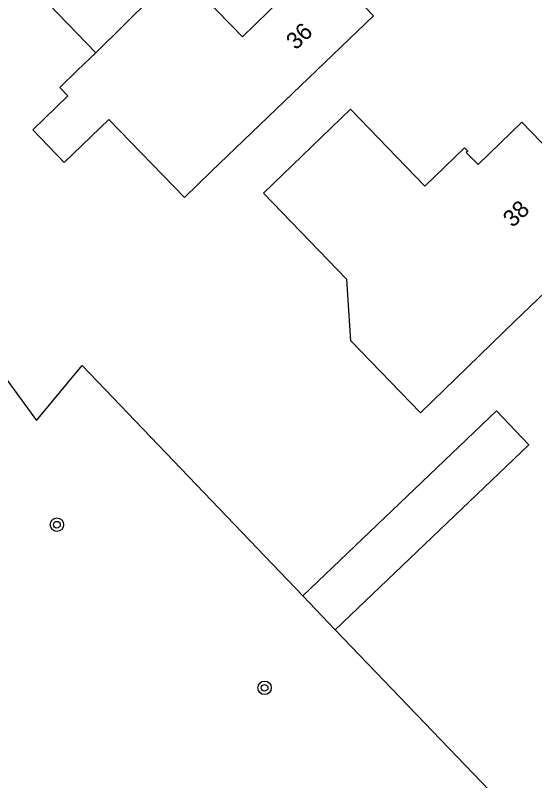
# Model space of a CAD drawing. Extents: x 137999 to 141000, y 397500 to 400501.
# Drawn here: x 138485.55 to 138516.5, y 399190.37 to 399235.95 of the extents above; entities that cross this region are included whole.
import ezdxf

# ---------------------------------------------------------------- set-up
doc = ezdxf.new("R2010")
doc.units = 0
for name, color, linetype in [('gg-afsc-erfafscheiding', 7, 'Continuous'), ('gg-anno-huisnummerreeks BGT', 7, 'Continuous'), ('gg-bbg-gedigitaliseerde bebouwing', 7, 'Continuous'), ('gg-bbg-gedigitaliseerde bijgebouw', 7, 'Continuous'), ('gg-bbg-hoofdgebouw', 7, 'Continuous'), ('gg-bbg-tussenscheiding', 7, 'Continuous'), ('gt-symb-boom', 7, 'Continuous')]:
    doc.layers.add(name, color=color, linetype=linetype)

# ---------------------------------------------------------------- blocks, each defined once
blk = doc.blocks.new('gt0-BOOM')
at = {"layer": 'gt-symb-boom'}
for radius in [0.4, 0.2]:
    blk.add_circle((0, 0), radius, dxfattribs=at)

msp = doc.modelspace()

# ---------------------------------------------------------------- linework, layer by layer
at = {"layer": 'gg-afsc-erfafscheiding'}
msp.add_line((138504.613, 399199.363), (138515.107, 399188.439), dxfattribs=at)
msp.add_lwpolyline([(138478.709, 399222.597), (138479.713, 399221.541), (138486.818, 399211.819), (138489.532, 399215.096), (138502.676, 399201.384)], dxfattribs=at)
at = {"layer": 'gg-bbg-gedigitaliseerde bebouwing'}
for p, q in [((138497.229, 399226.651), (138506.9, 399235.92)), ((138490.35, 399233.722), (138489.266, 399232.674)), ((138515.32, 399217.73), (138518.92, 399221.21))]:
    msp.add_line(p, q, dxfattribs=at)
for points in [[(138483.408, 399240.912), (138482.282, 399239.823), (138484.714, 399237.307), (138485.836, 399238.391), (138490.35, 399233.722)], [(138489.266, 399232.674), (138488.203, 399231.659), (138488.684, 399231.155), (138486.589, 399229.126), (138488.472, 399227.182), (138491.123, 399229.75), (138495.627, 399225.1), (138497.229, 399226.651)], [(138505.52, 399230.36), (138500.343, 399225.356), (138505.313, 399220.214)], [(138515.32, 399217.73), (138509.696, 399212.284), (138505.544, 399216.571), (138505.313, 399220.214)]]:
    msp.add_lwpolyline(points, dxfattribs=at)
at = {"layer": 'gg-bbg-gedigitaliseerde bijgebouw'}
msp.add_line((138502.676, 399201.384), (138504.613, 399199.363), dxfattribs=at)
msp.add_lwpolyline([(138504.613, 399199.363), (138516.149, 399210.376), (138514.215, 399212.401), (138502.676, 399201.384)], dxfattribs=at)
at = {"layer": 'gg-bbg-hoofdgebouw'}
for points in [[(138506.9, 399235.92), (138503.74, 399239.21), (138499.09, 399234.67), (138495.28, 399238.59)], [(138505.52, 399230.36), (138509.95, 399225.77), (138512.32, 399228.05), (138512.51, 399227.86), (138512.42, 399227.78), (138513.12, 399227.06), (138515.73, 399229.59), (138520.81, 399224.33), (138518.13, 399221.74), (138518.59, 399221.26), (138518.73, 399221.4), (138518.92, 399221.21)]]:
    msp.add_lwpolyline(points, dxfattribs=at)
at = {"layer": 'gg-bbg-tussenscheiding'}
msp.add_line((138495.28, 399238.59), (138490.35, 399233.722), dxfattribs=at)

# ---------------------------------------------------------------- block references
at = {"layer": 'gt-symb-boom'}
for p in [(138488.031, 399205.617), (138500.404, 399195.903)]:
    msp.add_blockref('gt0-BOOM', p, dxfattribs=at)

# ---------------------------------------------------------------- texts
at = {"layer": 'gg-anno-huisnummerreeks BGT'}
for s, rotation, p in [('36', 43.9, (138502.271, 399233.843)), ('38', 44, (138515.194, 399223.269))]:
    msp.add_text(s, height=1, rotation=rotation, dxfattribs=at).set_placement(p)

doc.saveas('drawing.dxf')
